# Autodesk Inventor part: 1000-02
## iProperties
Created: 2007-03
Part Number: 1000-02
Document SubType Name: Modeling
Designer: Andy Moles
Material: Steel
Mass: 8.73625 g
Surface Area: 13.3576 cm^2
Volume: 1.1129 cm^3
Density: 7.85 g/cm^3
Author: Andy Moles
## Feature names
1. Base1
